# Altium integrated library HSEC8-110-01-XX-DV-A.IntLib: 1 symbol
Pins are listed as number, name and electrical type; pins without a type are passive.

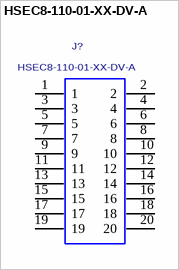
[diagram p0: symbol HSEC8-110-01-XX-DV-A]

## HSEC8-110-01-XX-DV-A
designator J?
0.8MM HIGH SPEED ASSEMBLY.; MANUFACTURER: SAMTEC
footprint HSEC8-110-01-XX-DV-A
footprint HSEC8-110-01-XX-DV-A
pins: 1, 2, 3, 4, 5, 6, 7, 8, 9, 10, 11, 12, 13, 14, 15, 16, 17, 18, 19, 20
